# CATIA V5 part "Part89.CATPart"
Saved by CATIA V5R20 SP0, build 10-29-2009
Part number: FA 053000-1
Revision: ANY
Definition: UNKNOWN
Nomenclature: FA 053000-1
Source: Unknown
Bounding box of the stored display mesh (mm): x -1.9 to 1.9, y -1.1 to 2.45, z -1.9 to 1.9
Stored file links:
  C:\Users\Utente\Desktop\IO LAVORO\3D X SITO CF\CUMSA\3D files FA\FA 053012-21\Part89.CATPart

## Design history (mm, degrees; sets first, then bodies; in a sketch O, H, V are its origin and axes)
Body1 "Cortar-Extruir1" (main body)
  Solid1: solid without history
